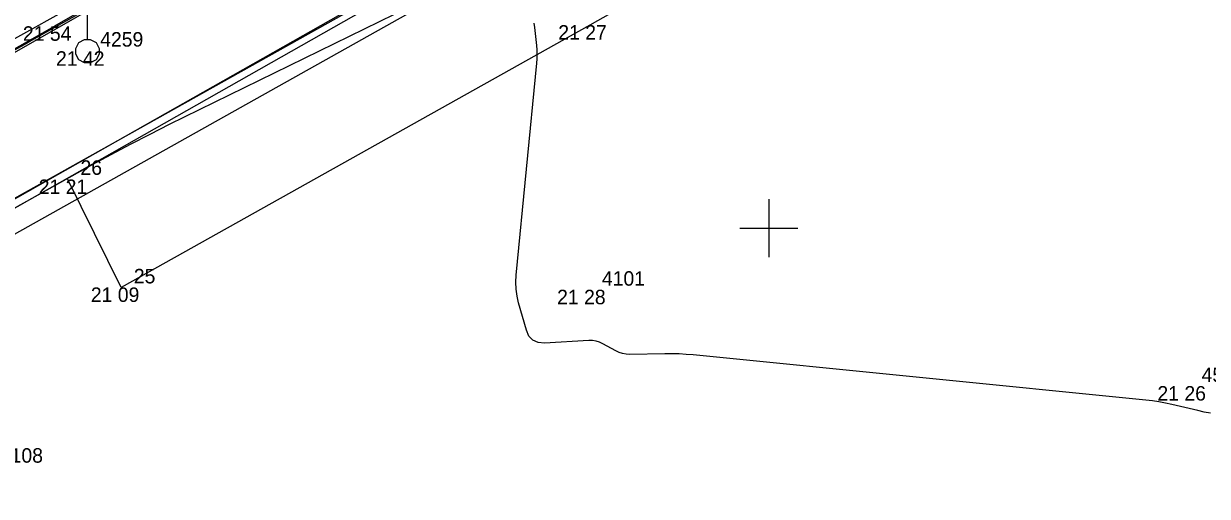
# Model space of a CAD drawing. Extents: x -702257 to -701487, y -1009871 to -1008841.
# Drawn here: x -701987.85 to -701967.44, y -1009629.62 to -1009621.47 of the extents above; entities that cross this region are included whole.
import ezdxf

# ---------------------------------------------------------------- set-up
doc = ezdxf.new("R2010")
doc.units = 0
for name, color, linetype in [('Ex_Minor Contours', 7, 'Continuous'), ('Z_body', 7, 'Continuous'), ('Z_body_cisla', 7, 'Continuous'), ('Z_body_vysky_redukovane', 7, 'Continuous'), ('Z_hektometricka_sit', 7, 'Continuous'), ('Z_katastr_hranice', 7, 'Continuous'), ('Z_komunikace', 7, 'Continuous'), ('Z_obruba', 7, 'Continuous'), ('Z_rozhranni', 7, 'Continuous'), ('Z_site_vo_znaky', 7, 'Continuous')]:
    doc.layers.add(name, color=color, linetype=linetype)

# ---------------------------------------------------------------- blocks, each defined once
blk = doc.blocks.new('POINT_DISPLAY')
blk.add_line((0, 0), (0, 0))
blk = doc.blocks.new('Z13')
for p, q in [((0, 0.88), (0.45, 1.1)), ((0.4, 1.07), (0.5, 0.88)), ((0, 0.2), (0, 0.88)), ((0.15, 0.7), (0.05, 0.9)), ((0.5, 0.88), (0.15, 0.7)), ((-0.2, 0.05), (-0.15, 0.15)), ((-0.2, -0.05), (-0.2, 0.05)), ((-0.15, 0.15), (-0.05, 0.2)), ((-0.05, 0.2), (0.05, 0.2)), ((0.05, 0.2), (0.15, 0.15)), ((0.15, 0.15), (0.2, 0.05)), ((0.2, 0.05), (0.2, -0.05)), ((-0.15, -0.15), (-0.2, -0.05)), ((-0.05, -0.2), (-0.15, -0.15)), ((0.05, -0.2), (-0.05, -0.2)), ((0.15, -0.15), (0.05, -0.2)), ((0.2, -0.05), (0.15, -0.15))]:
    blk.add_line(p, q)

msp = doc.modelspace()

# ---------------------------------------------------------------- linework, layer by layer
at = {"layer": 'Ex_Minor Contours'}
for points in [[(-701986.598, -1009621.138), (-701987.672, -1009621.743), (-701987.841, -1009621.837), (-701988.01, -1009621.931)], [(-701981.462, -1009621.318), (-701985.338, -1009623.215), (-701985.676, -1009623.383), (-701986.013, -1009623.556), (-701986.346, -1009623.734), (-701986.678, -1009623.915), (-701988.244, -1009624.788)], [(-701967.385, -1009628.189), (-701967.497, -1009628.168), (-701967.608, -1009628.143), (-701968.052, -1009628.037), (-701968.164, -1009628.012), (-701968.276, -1009627.991), (-701968.388, -1009627.974), (-701968.502, -1009627.961), (-701976.307, -1009627.183), (-701976.428, -1009627.173), (-701976.55, -1009627.166), (-701976.672, -1009627.163), (-701976.794, -1009627.164), (-701977.399, -1009627.175), (-701977.462, -1009627.172), (-701977.523, -1009627.161), (-701977.583, -1009627.142), (-701977.64, -1009627.115), (-701977.865, -1009626.99), (-701977.922, -1009626.963), (-701977.981, -1009626.945), (-701978.042, -1009626.935), (-701978.105, -1009626.935), (-701978.871, -1009626.979), (-701978.981, -1009626.97), (-701979.07, -1009626.93), (-701979.137, -1009626.86), (-701979.181, -1009626.758), (-701979.316, -1009626.288), (-701979.343, -1009626.171), (-701979.36, -1009626.052), (-701979.365, -1009625.932), (-701979.359, -1009625.811), (-701979.003, -1009622.155), (-701978.997, -1009622.079), (-701978.996, -1009622.002), (-701978.998, -1009621.926), (-701979.004, -1009621.849), (-701979.037, -1009621.543), (-701979.046, -1009621.467)]]:
    msp.add_lwpolyline(points, dxfattribs=at)
at = {"layer": 'Z_hektometricka_sit'}
for p, q in [((-701975, -1009624.5), (-701975, -1009625.5)), ((-701975, -1009624.5), (-701975, -1009625.5)), ((-701975.5, -1009625), (-701974.5, -1009625)), ((-701975.5, -1009625), (-701974.5, -1009625))]:
    msp.add_line(p, q, dxfattribs=at)
at = {"layer": 'Z_katastr_hranice'}
for p, q in [((-702014.27, -1009636.43), (-701959.3, -1009605.67)), ((-702013.06, -1009638.53), (-701957.87, -1009607.59))]:
    msp.add_line(p, q, dxfattribs=at)
at = {"layer": 'Z_komunikace'}
msp.add_line((-701980.98, -1009621.17), (-701990.13, -1009626.29), dxfattribs=at)
at = {"layer": 'Z_obruba'}
for p, q in [((-701981.25, -1009620.67), (-701990.38, -1009625.84)), ((-701989.56, -1009622.86), (-701985.77, -1009620.69)), ((-701985.8, -1009620.64), (-701987.32, -1009621.52)), ((-701990.32, -1009625.96), (-701981.19, -1009620.79)), ((-701998.58, -1009627.85), (-701987.32, -1009621.52))]:
    msp.add_line(p, q, dxfattribs=at)
at = {"layer": 'Z_rozhranni'}
for p, q in [((-701966.58, -1009614.98), (-701978.09, -1009621.5)), ((-701978.09, -1009621.5), (-701986.17, -1009626.02)), ((-701986.17, -1009626.02), (-701987.09, -1009624.16))]:
    msp.add_line(p, q, dxfattribs=at)

# ---------------------------------------------------------------- block references
at = {"layer": 'Z_body'}
for p in [(-701987.32, -1009621.52), (-701978.09, -1009621.5), (-701986.75, -1009621.95), (-701987.09, -1009624.16), (-701986.17, -1009626.02), (-701978.11, -1009626.06), (-701967.76, -1009627.72)]:
    msp.add_blockref('POINT_DISPLAY', p, dxfattribs=at)
at = {"layer": 'Z_site_vo_znaky'}
msp.add_blockref('Z13', (-701986.75, -1009621.95), dxfattribs=at)

# ---------------------------------------------------------------- texts
at = {"layer": 'Z_body_cisla'}
for s, p in [('4259', (-701986.53, -1009621.87)), ('26', (-701986.87, -1009624.08)), ('25', (-701985.95, -1009625.95)), ('4101', (-701977.88, -1009625.99)), ('4510', (-701967.54, -1009627.65)), ('4108', (-701988.26, -1009629.04))]:
    msp.add_text(s, height=0.25, dxfattribs=at).set_placement(p)
at = {"layer": 'Z_body_vysky_redukovane'}
for s, p in [('21 54', (-701987.862, -1009621.77)), ('21 27', (-701978.632, -1009621.75)), ('21 42', (-701987.292, -1009622.2)), ('21 21', (-701987.59, -1009624.41)), ('21 09', (-701986.691, -1009626.27)), ('21 28', (-701978.652, -1009626.31)), ('21 26', (-701968.302, -1009627.97))]:
    msp.add_text(s, height=0.25, dxfattribs=at).set_placement(p)

doc.saveas('drawing.dxf')
